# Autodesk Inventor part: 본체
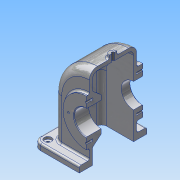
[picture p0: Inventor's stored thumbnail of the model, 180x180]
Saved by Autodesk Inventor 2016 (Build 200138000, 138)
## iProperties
Created: 2018-08
Part Number: 본체
Material: 알루미늄 6061
Document SubType Name: Modeling
Designer: Administrator
Density: 2.7 g/cm^3
Appearance: 알루미늄 - 평지
Mass: 1092.08 g
Surface Area: 1182.21 cm^2
Volume: 404.475 cm^3
Author: Administrator
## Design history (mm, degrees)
sketch "스케치1"
  geometry: L1 (-75, -55)-(75, -55); L2 (75, -55)-(75, 55); L3 (75, 55)-(-75, 55); L4 (-75, 55)-(-75, -55); L5 (-75, -55)-(75, 55); L6 (75, -55)-(-75, 55); 1 further point
  constraints: 12 end point, 2 midpoint, 2 parallel, 1 horizontal, 1 perpendicular
  dimensions: "d0" = 150 distance of L3.end L2.end; "d1" = 110 distance of L2.end L1.end
extrude "돌출1" new body sketch "스케치1" distance "d2" = 10; taper "d3" = 0 deg
sketch "스케치2"
  geometry: L1 (-58, 78)-(58, 78); L2 (58, 78)-(58, 0); L3 (58, 0)-(-58, 0); L4 (-58, 0)-(-58, 78); L5 (-58, 78)-(58, 0); L6 (58, 78)-(-58, 0); L7 (-75, 0)-(75, 0) reference; A1 r 58 centre (0, 78) between (-58, 78) and (58, 78); A2 r 58 centre (0, 78) between (58, 78) and (-58, 78); 4 further points
  constraints: 12 end point, 5 midpoint, 4 point on circle, 2 centre point, 2 parallel, 1 horizontal, 1 perpendicular, 1 point on line, 1 vertical alignment
  dimensions: "d4" = 78 distance of L1.end L2.end; "d5" = 58 distance from line of L2 point (0, 39)
extrude "돌출2" join sketch "스케치2" stored distance "d6" = 77; taper "d7" = 0 deg
sketch "스케치3"
  geometry: L1 (58, 10)-(-58, 10) reference; L2 (58, 10)-(58, 78) reference; L3 (-58, 78)-(-58, 10) reference; L4 (52, 78)-(52, 0); L5 (-52, 0)-(-52, 78); L6 (-75, 0)-(75, 0) reference; L7 (52, 0)-(-52, 0); A1 r 58 centre (0, 78) between (58, 78) and (-58, 78) reference; A2 r 52 centre (0, 78) between (52, 78) and (-52, 78); 1 further point
  constraints: 6 end point, 2 point on circle, 2 point on line, 1 centre point, 1 collinear, 1 other
  dimensions: "d8" = 6 radial gap between concentric circles of A1 A2; "d9" = 6 distance between parallel lines of L3 L5
extrude "돌출3" cut sketch "스케치3" stored distance "d10" = 67; taper "d11" = 0 deg
sketch "스케치4"
  geometry: L1 (-99.407, 65)-(95.784, 65); L2 (-43.5, 65)-(-43.5, 103); L3 (-43.5, 103)-(-38.5, 103); L4 (-38.5, 136)-(-38.5, 78) reference; L5 (-38.5, 103)-(-38.5, 104.747); L6 (-33.5, 130)-(-33.5, 78) reference; L7 (-38.5, 104.747)-(-33.5, 104.747); L8 (-33.5, 104.747)-(-19.5, 93); L9 (-19.5, 93)-(-19.5, 65); L10 (38.5, 78)-(38.5, 136) reference; L11 (48.5, 65)-(48.5, 103); L12 (48.5, 103)-(38.5, 103); L13 (38.5, 103)-(38.5, 65); 1 further point
  constraints: 20 end point, 9 point on line, 5 perpendicular, 1 horizontal, 1 vertical
  dimensions: "d12" = 65 vertical distance of point (0, 0) L1.start; "d13" = 5 distance between parallel lines of L4 L2; "d14" = 76 diameter of L3 L1; "d15" = 50 deg angle of L9 L8; "d16" = 56 diameter of L8.end L1; "d17" = 24 distance between parallel lines of L9 L2; "d18" = 76 diameter of L12 L1; "d19" = 87 distance between parallel lines of L11 L4
revolve "회전1" sketch "스케치4" stored, may be unused: angle "d20" = 90 deg
sketch "스케치5"
  geometry: C1 r 38 at (0, 0) reference; C2 r 20 at (0, 0); 1 further point
  constraints: 1 centre point, 1 coincident
  dimensions: "d21" = 40 diameter of C2
extrude "돌출4" cut sketch "스케치5" stored distance "d22" = 67; taper "d23" = 0 deg
node "작업 평면1"
sketch "스케치6"
  geometry: L1 (-75, -55)-(75, -55) reference; L2 (-75, 55)-(-75, -55) reference; C1 r 6 at (0, 0); 1 further point
  constraints: 1 centre point
  dimensions: "d25" = 12 diameter of C1; "d26" = 55 distance from line of C1.centre L1; "d27" = 75 distance from line of C1.centre L2
extrude "돌출5" join sketch "스케치6" stored distance "d28" = 0; taper "d29" = 5 deg
sketch "스케치7" dims "d30" = 58
  geometry: L1 (0, 0)-(0, 29); C1 r 38 at (0, 0) reference; 2 further points
  constraints: 2 coincident, 2 end point, 1 vertical, 1 vertical alignment, 2 other
hole "구멍1" sketch "스케치7" at (0, 29) diameter "d31" = 3.242; stored, may be unused: countersink angle "d35" = 90 deg, drill point angle "d37" = 118 deg; dims "d32" = 8, "d33" = 4, "d34" = 2, "d36" = 10
sketch "스케치8" dims "d41" = 58
  geometry: L1 (0, 0)-(0, -29); C1 r 38 at (0, 0) reference; 2 further points
  constraints: 2 coincident, 2 end point, 1 vertical, 1 vertical alignment, 2 other
hole "구멍2" sketch "스케치8" at (0, -29) diameter "d42" = 3.242; stored, may be unused: countersink angle "d46" = 90 deg, drill point angle "d48" = 118 deg; dims "d43" = 8, "d44" = 4, "d45" = 2, "d47" = 10
fillet "모깎기1" dims "d52" = 12
fillet "모깎기2" dims "d53" = 8
fillet "모깎기3" dims "d54" = 13
hole "구멍3" diameter "d57" = 4.459; stored, may be unused: countersink angle "d61" = 90 deg, drill point angle "d63" = 118 deg; dims "d55" = 10, "d56" = 10, "d58" = 100, "d59" = 4, "d60" = 2, "d62" = 12.8
fillet "모깎기4" dims "d64" = 3
sketch "스케치9"
  geometry: A1 r 12 centre (-63, 43) between (-63, 55) and (-75, 43) reference; A2 r 12 centre (-63, -43) between (-75, -43) and (-63, -55) reference; A3 r 12 centre (63, -43) between (63, -55) and (75, -43) reference; A4 r 12 centre (63, 43) between (75, 43) and (63, 55) reference; 4 further points
  constraints: 4 coincident
hole "구멍4" sketch "스케치9" at (-63, 43), (-63, -43), (63, -43), (63, 43) diameter "d65" = 5; stored, may be unused: countersink angle "d69" = 90 deg, drill point angle "d71" = 118 deg; dims "d66" = 100, "d67" = 12, "d68" = 4, "d70" = 12.8
sketch "스케치10"
  geometry: L1 (0, -13)-(65, -13) reference; L2 (78, -17.5)-(78, -29.5) reference; 2 further points
  constraints: 1 other
  dimensions: "d72" = 38.5 distance from line of L1 point (38, 25.5); "d73" = 40 distance from line of L2 point (38, 25.5)
feature "엠보싱1" sketch "스케치10" dims "d0" = 150, "d1" = 110, "d74" = 0.5, "d75" = 0
chamfer "모따기1" distance "d76" = 1; stored, may be unused: second distance "d77" = 2, angle "d78" = 45 deg
sketch "스케치11"
  geometry: L1 (-90.448, 159.861)-(80.912, 159.861); L2 (80.912, 159.861)-(80.912, -19.071); L3 (80.912, -19.071)-(-90.448, -19.071); L4 (-90.448, -19.071)-(-90.448, 159.861); 1 further point
  constraints: 8 end point, 2 parallel, 1 horizontal, 1 perpendicular
extrude "돌출6" cut sketch "스케치11" stored distance "d79" = 10; taper "d80" = 0 deg
node "솔리드1"
pattern_circular "원형 패턴1" dims angle "d39" = 360 deg
pattern_circular "원형 패턴2" dims angle "d50" = 360 deg
node "투영된 루프1"
other parameters: "d24" = 142
